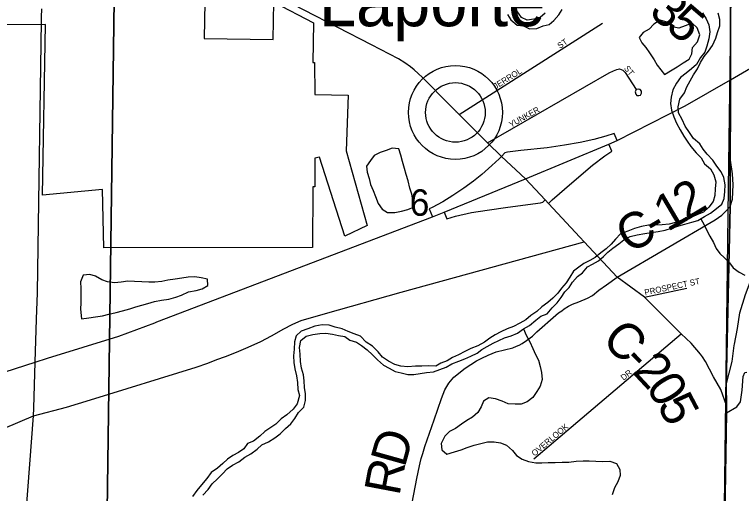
# Model space of a CAD drawing. Extents: x 1857828 to 2277390, y 930619 to 1324581.
# Drawn here: x 2080841 to 2086916, y 1210395 to 1214402 of the extents above; entities that cross this region are included whole.
import ezdxf

# ---------------------------------------------------------------- set-up
doc = ezdxf.new("R2010")
doc.units = 0
for name, color, linetype in [('GM_X_City_Street', 7, 'Continuous'), ('GM_X_Corporation', 7, 'Continuous'), ('GM_X_County_Road', 7, 'Continuous'), ('GM_X_County_Road_Text', 7, 'Continuous'), ('GM_X_Interchange_Ramps', 7, 'Continuous'), ('GM_X_Major_River', 7, 'Continuous'), ('GM_X_Minor_Lake', 7, 'Continuous'), ('GM_X_Minor_River', 7, 'Continuous'), ('GM_X_Section', 7, 'Continuous'), ('GM_X_Section_Text', 7, 'Continuous'), ('GM_X_State_Route', 7, 'Continuous'), ('GM_X_Township', 7, 'Continuous'), ('GM_X_Township_Road', 7, 'Continuous'), ('GM_X_Township_Road_Text', 7, 'Continuous'), ('GM_X_Township_Subdivision', 7, 'Continuous'), ('GM_X_Township_Subdivision_Text', 7, 'Continuous'), ('GM_X_Unincorporated', 7, 'Continuous'), ('GM_X_Unincorporated_Location', 7, 'Continuous'), ('GM_X_Unincorporated_Text', 7, 'Continuous'), ('GM_X_US_Route', 7, 'Continuous')]:
    doc.layers.add(name, color=color, linetype=linetype)

msp = doc.modelspace()

# ---------------------------------------------------------------- linework, layer by layer
at = {"layer": 'GM_X_City_Street'}
msp.add_lwpolyline([(2081066.6, 1214346.6), (2081067.1, 1214378.9), (2081068.2, 1214450.4)], dxfattribs=at)
at = {"layer": 'GM_X_Corporation'}
msp.add_lwpolyline([(2082431.7, 1214504.8), (2082426.4, 1214200.2), (2083003.5, 1214192.8), (2083008.7, 1214504.1), (2083340.5, 1214333.6), (2083332.8, 1214000.9), (2083348.9, 1214000.9), (2083349.6, 1213733.2), (2083627.9, 1213727.4), (2083613.9, 1213261.3), (2083786.8, 1212637.9), (2083600.3, 1212548.9), (2083390.2, 1213209.5), (2083351.1, 1213200.4), (2083351.7, 1212960.8), (2083335.2, 1212960.6), (2083330.6, 1212452.1), (2081588.3, 1212450.2), (2081574.8, 1212939.6), (2081074.2, 1212891.7), (2081100.6, 1214319.6), (2078910.7, 1214305.6)], dxfattribs=at)
at = {"layer": 'GM_X_County_Road'}
for points in [[(2084481.4, 1213642.1), (2084249.4, 1213874.3), (2084213, 1213908.4), (2084181.9, 1213938), (2084150, 1213963.7), (2084103.8, 1213997.9), (2084049, 1214032.5), (2083824.5, 1214148.2), (2082699.2, 1214730.9), (2082586.9, 1214795.9), (2082546.1, 1214823.7), (2082500.7, 1214856.2), (2082438.5, 1214905.4), (2082371.7, 1214977.8), (2082055.3, 1215322), (2081693.4, 1215722.8), (2081081.5, 1216369.5), (2080916.1, 1216542.2), (2080871.6, 1216592.1), (2080789.2, 1216690.2), (2080649.8, 1216892.8), (2080547.6, 1217082.7)], [(2081001.8, 1211108.6), (2081013.7, 1211494.1), (2081024.2, 1211853.7), (2081031.5, 1212075), (2081035.5, 1212267), (2081066.6, 1214346.6)], [(2085565.4, 1212540.5), (2085302.8, 1212822.2), (2085275.7, 1212851.4), (2085111.3, 1213027.7), (2084910, 1213213.6), (2084793.3, 1213328.4), (2084556.9, 1213566.5), (2084481.4, 1213642.1)], [(2085878.9, 1212204), (2086695.4, 1212685.1), (2086753.3, 1212724.5), (2086780, 1212751.2), (2086821.5, 1212795.1), (2086841.4, 1212856.6), (2086847.2, 1212977.1), (2086842.5, 1213068.6), (2086822.7, 1213201.9), (2086823.8, 1213635.3)], [(2086589.8, 1211537.5), (2086575.2, 1211559.4), (2086495.8, 1211654), (2086413.5, 1211730.5), (2086105.7, 1212038.4), (2085878.9, 1212204), (2085602.9, 1212500.2), (2085565.4, 1212540.5)], [(2073594.6, 1207932.1), (2076220, 1209011.3), (2080999.8, 1211044.3), (2081275, 1211117.7), (2081474.9, 1211179.1), (2082358.5, 1211451.5), (2082456.5, 1211486.3), (2082532.4, 1211514.8), (2082604.4, 1211541.4), (2082696.3, 1211576.1), (2082794.2, 1211618.8), (2082898, 1211665.6), (2082987.9, 1211714.3), (2083091.7, 1211771.2), (2083161.6, 1211809.7), (2083191.6, 1211824), (2083235.5, 1211842.3), (2083439.5, 1211899.7), (2084071.3, 1212080.3), (2085602.9, 1212500.2)], [(2086791.5, 1211130), (2086745.3, 1211263.9), (2086684.1, 1211371), (2086649.7, 1211435), (2086616.3, 1211498.2), (2086589.8, 1211537.5)], [(2080937.3, 1210236.7), (2080999.8, 1211044.3), (2081001.8, 1211108.6)]]:
    msp.add_lwpolyline(points, dxfattribs=at)
at = {"layer": 'GM_X_Interchange_Ramps'}
for points in [[(2085877.3, 1213347.3), (2085852.6, 1213406.5), (2085782.4, 1213384.3), (2085683.6, 1213357.4), (2085568.5, 1213331.6), (2085437, 1213309.7), (2085292, 1213287.7), (2085073.7, 1213263.5), (2084961.2, 1213251.3), (2084939.5, 1213245.6), (2084910, 1213213.6)], [(2085302.8, 1212822.2), (2085335, 1212852.2), (2085499, 1212994), (2085671.1, 1213142.6), (2085773.4, 1213221.2), (2085832.5, 1213260), (2085808.1, 1213318.5)], [(2084910, 1213213.6), (2084892.7, 1213194.9), (2084830.8, 1213138.4), (2084747.4, 1213062.8), (2084676.1, 1213007.6), (2084595.3, 1212949.7), (2084505.1, 1212887.5), (2084421.5, 1212834.9), (2084332.4, 1212787.8), (2084306.4, 1212776), (2084333.6, 1212709.4)], [(2084431.2, 1212749.3), (2084454.6, 1212692.1), (2084527.4, 1212713.9), (2084660.1, 1212745.3), (2084790.3, 1212764.5), (2084963.7, 1212789.6), (2085237.6, 1212825.3), (2085255.1, 1212832.3), (2085275.7, 1212851.4)]]:
    msp.add_lwpolyline(points, dxfattribs=at)
at = {"layer": 'GM_X_Major_River'}
for points in [[(2084960, 1214403), (2084988.3, 1214357), (2085042.6, 1214313.1), (2085094.8, 1214307.3), (2085145, 1214283.5), (2085205.1, 1214285.8), (2085259.2, 1214306.1), (2085309.2, 1214318.4), (2085349.2, 1214352.7), (2085389.1, 1214399.1), (2085417, 1214445.4)], [(2085276.8, 1214412.6), (2085234.8, 1214378.3), (2085180.7, 1214361.9), (2085124.6, 1214353.6), (2085078.4, 1214377.5), (2085038.1, 1214433.5)], [(2086591.9, 1214415), (2086620.1, 1214366.9), (2086642.4, 1214316.8), (2086652.7, 1214258.6), (2086644.9, 1214198.4), (2086627.1, 1214136), (2086609.3, 1214087.8), (2086575.3, 1214043.2), (2086539.6, 1213983), (2086497.6, 1213946.6), (2086453.7, 1213910.3), (2086405.7, 1213873.9), (2086373.8, 1213827.6), (2086344, 1213773.2), (2086330.2, 1213710.9), (2086324.4, 1213656.6), (2086332.7, 1213602.5), (2086351, 1213546.3), (2086373.2, 1213492.2), (2086403.6, 1213436.2), (2086433.9, 1213384.1), (2086462.1, 1213342.1), (2086494.4, 1213298.1), (2086536.7, 1213246.1), (2086579, 1213204.1), (2086607.2, 1213152), (2086657.5, 1213112.1), (2086685.8, 1213062), (2086702.1, 1213001.9), (2086696.3, 1212943.6), (2086694.6, 1212887.4), (2086680.7, 1212839.1), (2086642.9, 1212790.8), (2086598.9, 1212748.4), (2086542.9, 1212726), (2086482.9, 1212697.6), (2086418.8, 1212681.2), (2086364.8, 1212662.9), (2086312.7, 1212648.6), (2086252.6, 1212642.3), (2086192.4, 1212640), (2086138.3, 1212639.7), (2086082.2, 1212627.4), (2086022.2, 1212613), (2085966.1, 1212590.7), (2085906.1, 1212568.3), (2085864.2, 1212521.9), (2085826.3, 1212479.6), (2085786.3, 1212443.2), (2085740.4, 1212408.9)], [(2085798.5, 1212415.2), (2085842.4, 1212447.5), (2085890.4, 1212483.9), (2085932.4, 1212516.2), (2085986.4, 1212544.6), (2086044.4, 1212558.9), (2086108.5, 1212569.3), (2086162.6, 1212579.6), (2086220.7, 1212587.9), (2086278.8, 1212598.2), (2086332.9, 1212614.6), (2086392.9, 1212632.9), (2086443, 1212649.2), (2086501.1, 1212665.6), (2086551.1, 1212677.9), (2086607.1, 1212712.3), (2086657.1, 1212740.6), (2086709.1, 1212779), (2086751, 1212815.4), (2086770.9, 1212861.6), (2086778.6, 1212921.9), (2086780.4, 1212978.2), (2086770.1, 1213038.3), (2086745.9, 1213086.4), (2086711.6, 1213134.4), (2086677.3, 1213184.5), (2086628.9, 1213234.4), (2086596.7, 1213274.4), (2086568.4, 1213320.5), (2086516.1, 1213364.4), (2086481.8, 1213414.4), (2086445.5, 1213468.5), (2086421.2, 1213522.6), (2086388.9, 1213578.7), (2086386.7, 1213628.8), (2086402.5, 1213693.2), (2086440.3, 1213745.6), (2086460.2, 1213797.9), (2086488, 1213846.2), (2086515.9, 1213898.6), (2086547.7, 1213948.9), (2086573.6, 1214001.2), (2086605.4, 1214049.6), (2086641.3, 1214095.9), (2086673.2, 1214144.3), (2086701, 1214204.7), (2086716.8, 1214252.9), (2086734.6, 1214307.2), (2086736.4, 1214361.5), (2086722.2, 1214413.6)], [(2085740.4, 1212408.9), (2085694.4, 1212368.5), (2085650.4, 1212344.2), (2085598.4, 1212319.8), (2085556.4, 1212289.5), (2085512.5, 1212255.2), (2085480.6, 1212204.8), (2085450.7, 1212158.5), (2085412.8, 1212112.1), (2085380.9, 1212069.8), (2085341, 1212029.4), (2085297.1, 1211993.1), (2085249.1, 1211956.7), (2085205.2, 1211918.3), (2085157.2, 1211884), (2085115.3, 1211847.6), (2085063.3, 1211819.3), (2085011.3, 1211790.9), (2084959.2, 1211772.6), (2084905.2, 1211748.2), (2084857.2, 1211721.9), (2084813.2, 1211693.6), (2084769.2, 1211661.2), (2084713.2, 1211630.8), (2084653.2, 1211608.4), (2084605.2, 1211582.1), (2084551.2, 1211555.8), (2084501.1, 1211531.4), (2084457.2, 1211505.1), (2084405.1, 1211484.8), (2084361.1, 1211460.5), (2084299, 1211462.2), (2084244.8, 1211459.9), (2084192.7, 1211459.6), (2084128.6, 1211455.3), (2084068.4, 1211459), (2084018.3, 1211472.8), (2083966, 1211500.7), (2083915.8, 1211534.6), (2083879.5, 1211580.6), (2083833.2, 1211626.6), (2083780.9, 1211662.4), (2083732.6, 1211710.4), (2083678.4, 1211730.2), (2083628.2, 1211750.1), (2083577.9, 1211773.9), (2083521.7, 1211787.7), (2083471.6, 1211803.5), (2083411.4, 1211805.2), (2083349.3, 1211794.9), (2083291.3, 1211772.5), (2083237.2, 1211752.2), (2083193.3, 1211713.8), (2083181.5, 1211663.6), (2083177.7, 1211603.3), (2083171.9, 1211547.1), (2083176.2, 1211490.9), (2083184.4, 1211438.7), (2083198.7, 1211380.5), (2083205, 1211322.3), (2083209.2, 1211264.1), (2083221.5, 1211214), (2083203.7, 1211145.6), (2083169.8, 1211099.3), (2083115.9, 1211052.8), (2083069.9, 1211018.5), (2083024, 1210976.1), (2082982, 1210947.8), (2082934.1, 1210913.4), (2082890.1, 1210875), (2082838.2, 1210832.6), (2082788.1, 1210814.3), (2082756.3, 1210768), (2082712.3, 1210737.6), (2082664.3, 1210713.3), (2082620.3, 1210683), (2082580.4, 1210646.6), (2082538.4, 1210606.3), (2082484.4, 1210571.9), (2082446.6, 1210521.5), (2082402.7, 1210467.1), (2082364.8, 1210418.7), (2082328.9, 1210370.3)], [(2082415.1, 1210380.8), (2082459, 1210427.2), (2082492.9, 1210475.6), (2082536.8, 1210517.9), (2082578.7, 1210558.3), (2082618.6, 1210602.7), (2082662.6, 1210633), (2082716.6, 1210659.3), (2082766.6, 1210697.7), (2082814.6, 1210728.1), (2082868.5, 1210766.5), (2082908.5, 1210802.8), (2082962.5, 1210827.2), (2083016.5, 1210859.6), (2083060.4, 1210893.9), (2083106.4, 1210938.3), (2083150.3, 1210976.7), (2083184.2, 1211023.1), (2083214.1, 1211071.4), (2083258, 1211117.8), (2083273.8, 1211174.1), (2083273.5, 1211228.3), (2083265.3, 1211282.5), (2083261, 1211336.6), (2083254.8, 1211388.8), (2083240.5, 1211443), (2083230.3, 1211499.1), (2083228, 1211561.4), (2083223.8, 1211615.6), (2083233.5, 1211673.8), (2083277.5, 1211712.2), (2083333.6, 1211726.5), (2083393.7, 1211734.9), (2083443.8, 1211735.1), (2083497.9, 1211729.3), (2083548.1, 1211717.6), (2083600.3, 1211709.8), (2083644.5, 1211677.9), (2083698.7, 1211660.1), (2083740.9, 1211632.1), (2083789.2, 1211596.2), (2083831.5, 1211554.3), (2083875.7, 1211512.3), (2083924.1, 1211468.4), (2083972.3, 1211442.5), (2084022.5, 1211414.6), (2084072.7, 1211404.8), (2084128.9, 1211391.1), (2084179, 1211391.3), (2084231.1, 1211399.6), (2084283.2, 1211405.9), (2084341.3, 1211414.2), (2084395.3, 1211432.5), (2084447.4, 1211452.8), (2084495.4, 1211479.2), (2084555.4, 1211501.6), (2084605.4, 1211521.9), (2084655.5, 1211544.2), (2084707.5, 1211568.6), (2084747.5, 1211598.9), (2084791.4, 1211625.2), (2084841.4, 1211653.5), (2084887.4, 1211675.9), (2084935.5, 1211698.2), (2084991.5, 1211714.5), (2085043.6, 1211736.8), (2085093.5, 1211771.2), (2085145.5, 1211799.6), (2085197.5, 1211844), (2085239.4, 1211878.3), (2085293.5, 1211896.7), (2085333.3, 1211949.1), (2085377.3, 1211989.5), (2085409.2, 1212035.8), (2085441, 1212082.1), (2085477, 1212118.4), (2085504.8, 1212162.8), (2085544.7, 1212209.1), (2085586.7, 1212241.5), (2085628.6, 1212289.9), (2085672.6, 1212314.2), (2085720.6, 1212342.5), (2085762.5, 1212378.9), (2085798.5, 1212415.2)]]:
    msp.add_lwpolyline(points, dxfattribs=at)
at = {"layer": 'GM_X_Minor_Lake'}
for points in [[(2086272.6, 1213899.9), (2086322.5, 1213932.3), (2086378.5, 1213964.8), (2086430.5, 1213997.3), (2086478.4, 1214027.7), (2086502.2, 1214072.1), (2086508, 1214126.4), (2086547.8, 1214172.8), (2086569.6, 1214231.2), (2086545.2, 1214291.3), (2086504.9, 1214329.3), (2086444.8, 1214306.8), (2086392.8, 1214288.4), (2086338.6, 1214298.1), (2086294.2, 1214338), (2086236, 1214353.7), (2086184, 1214321.3)], [(2086184, 1214321.3), (2086144.1, 1214278.8), (2086094.2, 1214250.4), (2086060.3, 1214210), (2086084.6, 1214166), (2086116.9, 1214126), (2086147.2, 1214081.9), (2086185.6, 1214023.9), (2086212, 1213977.9), (2086272.6, 1213899.9)], [(2084180.8, 1212794.1), (2084168.5, 1212848.3), (2084160.2, 1212900.5), (2084145.9, 1212950.6), (2084131.5, 1213010.8), (2084115.2, 1213064.9), (2084100.9, 1213115.1), (2084082.5, 1213171.2), (2084070.2, 1213225.4), (2084053.8, 1213277.5), (2083997.7, 1213283.2), (2083945.6, 1213264.8), (2083897.6, 1213248.5), (2083845.6, 1213222), (2083815.7, 1213179.6), (2083781.9, 1213133.2), (2083788.2, 1213083)], [(2083788.2, 1213083), (2083804.5, 1213030.9), (2083816.8, 1212980.7), (2083839.1, 1212930.6), (2083857.5, 1212878.5), (2083879.8, 1212822.4), (2083914.2, 1212772.4), (2083958.5, 1212744.5), (2084018.6, 1212746.9), (2084074.7, 1212757.3), (2084126.8, 1212769.7), (2084180.8, 1212794.1)], [(2082401.2, 1212200.6), (2082347, 1212208.3), (2082290.8, 1212203.9), (2082238.7, 1212195.6), (2082184.6, 1212187.2), (2082122.5, 1212178.8), (2082072.4, 1212168.4), (2082012.3, 1212162), (2081962.2, 1212161.7), (2081904, 1212165.4), (2081843.8, 1212169), (2081787.6, 1212170.7), (2081731.5, 1212164.3), (2081677.4, 1212158), (2081617.2, 1212165.6), (2081569, 1212183.4), (2081518.7, 1212213.2), (2081470.4, 1212227), (2081414.3, 1212222.7), (2081392.6, 1212166.3), (2081394.9, 1212110), (2081395.2, 1212059.8), (2081393.5, 1211989.5), (2081391.8, 1211937.2), (2081400.3, 1211856.9)], [(2081400.3, 1211856.9), (2081460.4, 1211863.3), (2081518.5, 1211871.7), (2081574.6, 1211882.1), (2081628.7, 1211896.5), (2081688.8, 1211908.9), (2081742.9, 1211923.3), (2081804.9, 1211939.8), (2081855, 1211956.1), (2081905, 1211970.5), (2081955.1, 1211984.9), (2082009.2, 1212001.3), (2082069.3, 1212011.7), (2082129.4, 1212022.1), (2082187.5, 1212036.5), (2082235.5, 1212054.9), (2082293.5, 1212083.4), (2082357.6, 1212093.8), (2082407.7, 1212108.2), (2082455.7, 1212134.6), (2082453.4, 1212186.8), (2082401.2, 1212200.6)]]:
    msp.add_lwpolyline(points, dxfattribs=at)
at = {"layer": 'GM_X_Minor_River'}
for points in [[(2086577.6, 1212694.2), (2086604.3, 1212642.1), (2086626.6, 1212594.1), (2086653, 1212548), (2086683.3, 1212495.9), (2086703.7, 1212445.8), (2086736, 1212401.8), (2086774.3, 1212365.9), (2086816.6, 1212324), (2086846.9, 1212284), (2086897.3, 1212246.1), (2086945.6, 1212220.3)], [(2085095.8, 1211772.5), (2085117.3, 1211720.9), (2085147.6, 1211664.8), (2085172, 1211608.7), (2085194.3, 1211558.6), (2085218.7, 1211510.6), (2085235, 1211456.4), (2085245.3, 1211406.2), (2085251.6, 1211350), (2085233.9, 1211293.7), (2085206.1, 1211247.3), (2085172.3, 1211196.8), (2085124.3, 1211162.4), (2085076.3, 1211142), (2085024.2, 1211141.7), (2084966, 1211145.4), (2084915.7, 1211167.2), (2084861.5, 1211186.9), (2084805.3, 1211196.6), (2084761.3, 1211168.2), (2084741.5, 1211119.9), (2084713.7, 1211071.5), (2084667.8, 1211033), (2084619.8, 1211004.6), (2084575.8, 1210974.2), (2084525.9, 1210939.8), (2084475.9, 1210913.3), (2084436, 1210874.9), (2084406.2, 1210814.4), (2084412.6, 1210760.2), (2084452.9, 1210724.3), (2084516.9, 1210742.8), (2084573, 1210759.2), (2084625, 1210779.6), (2084681.1, 1210800.1), (2084739.2, 1210814.5), (2084793.2, 1210826.9), (2084849.4, 1210827.2), (2084903.6, 1210817.5), (2084953.8, 1210799.7), (2085002.2, 1210755.8), (2085036.5, 1210713.8), (2085082.8, 1210682), (2085137.1, 1210662.2), (2085197.3, 1210650.5), (2085247.4, 1210652.8), (2085301.6, 1210653.2), (2085359.7, 1210655.5), (2085417.9, 1210657.9), (2085474, 1210656.2), (2085536.2, 1210664.6), (2085592.3, 1210667), (2085642.4, 1210667.3), (2085700.6, 1210665.6), (2085756.8, 1210664), (2085814.9, 1210664.3), (2085871.2, 1210644.6), (2085899.5, 1210596.5), (2085901.8, 1210546.3), (2085882.1, 1210492), (2085854.2, 1210443.6), (2085834.5, 1210385.2)]]:
    msp.add_lwpolyline(points, dxfattribs=at)
at = {"layer": 'GM_X_Section'}
for points in [[(2076344.3, 1215732.7), (2081688.8, 1215745.2), (2081611.5, 1210047.1), (2076246.6, 1210012.2)], [(2086844.8, 1215767), (2086806.5, 1212949.4), (2086771.6, 1210288), (2086769.4, 1210081), (2081611.5, 1210047.1), (2081688.8, 1215745.2)]]:
    msp.add_lwpolyline(points, close=True, dxfattribs=at)
at = {"layer": 'GM_X_State_Route'}
for points in [[(2086857.4, 1211643.8), (2086882.1, 1211774.5), (2086903.1, 1211906.4), (2086950.9, 1212059.5), (2087023.6, 1212253.5), (2087393.1, 1212824.7), (2087525.4, 1213089.5), (2087611.3, 1213406.7), (2087640.8, 1213663.6), (2087647.8, 1213865.6), (2087640.7, 1213980.6), (2087639.6, 1213999), (2087621.7, 1214291.1)], [(2086788.6, 1211286.5), (2086788.2, 1211303.5), (2086840, 1211499.1), (2086855.3, 1211633), (2086857.4, 1211643.8)], [(2086784.2, 1210601.2), (2086792.2, 1211070.7), (2086791.5, 1211130), (2086788.6, 1211286.5)], [(2086747.3, 1208327.6), (2086747.3, 1208327.6), (2086750.2, 1208539), (2086754.4, 1208841.7), (2086784.2, 1210601.2)]]:
    msp.add_lwpolyline(points, dxfattribs=at)
at = {"layer": 'GM_X_Township'}
for points in [[(2067771.4, 1221365.5), (2071559.9, 1221318), (2072926.4, 1221321.4), (2074729.4, 1221325.9), (2074869.3, 1221327.3), (2075410.3, 1221332.8), (2076347.8, 1221341.6), (2076980.3, 1221347.6), (2077896.6, 1221356.3), (2078876.9, 1221357.6), (2084360.8, 1221334.4), (2086459.3, 1221290.7), (2086885, 1221290.7), (2086885.2, 1220532.6), (2086868.6, 1218191.5), (2086826, 1214466.2), (2086824.4, 1213856.5), (2086823.8, 1213635.3), (2086822.7, 1213201.9), (2086821.5, 1212795.1), (2086788.3, 1211303.5), (2086791.5, 1211130), (2086792.2, 1211070.7), (2086754.4, 1208841.7)], [(2086754.4, 1208841.7), (2086792.2, 1211070.7), (2086791.5, 1211130), (2086788.3, 1211303.5), (2086821.5, 1212795.1), (2086822.7, 1213201.9), (2086823.8, 1213635.3), (2086824.4, 1213856.5), (2086826, 1214466.2), (2086868.6, 1218191.5), (2086885.2, 1220532.6), (2086885, 1221290.7), (2090249.5, 1221329.8)]]:
    msp.add_lwpolyline(points, dxfattribs=at)
at = {"layer": 'GM_X_Township_Road'}
msp.add_lwpolyline([(2084112.4, 1210040), (2084203.9, 1210520.1), (2084225.4, 1210626.6), (2084231.3, 1210650.7), (2084239.1, 1210686.9), (2084252.9, 1210729.1), (2084270.6, 1210787.4), (2084347.4, 1211010.6), (2084408.6, 1211189.5), (2084436.2, 1211261.9), (2084469.9, 1211318.3), (2084511.7, 1211368.8), (2084607.4, 1211443.6), (2084703.2, 1211504.4), (2084747.1, 1211526.7), (2084799.1, 1211551.2), (2084865, 1211579.6), (2085005, 1211614.6), (2085034.9, 1211628.9), (2085059, 1211637), (2085082.9, 1211649.2), (2085120.8, 1211673.6), (2085168.7, 1211710), (2085206.5, 1211746.3), (2085366, 1211887.8), (2085387.9, 1211906), (2085413.8, 1211924.2), (2085435.8, 1211940.4), (2085471.7, 1211962.7), (2085505.6, 1211978.9), (2085557.6, 1211997.3), (2085629.5, 1212027.9), (2085671.5, 1212052.2), (2085723.3, 1212094.7), (2085789.1, 1212141.2), (2085878.9, 1212204)], dxfattribs=at)
at = {"layer": 'GM_X_Township_Subdivision'}
for points in [[(2084556.9, 1213566.5), (2085756.1, 1214330.2)], [(2084793.3, 1213328.4), (2085812, 1213913.2), (2085846, 1213931.5), (2085873.9, 1213941.6), (2085898, 1213947.8), (2085926, 1213937.9), (2085944.1, 1213917.9), (2085976.4, 1213870), (2086036.9, 1213776), (2086028.9, 1213755.6), (2086033.1, 1213735.9), (2086043.2, 1213725.6), (2086059, 1213723.6), (2086073.1, 1213728.1), (2086080.7, 1213744.3), (2086081, 1213760.2), (2086068.9, 1213774.2), (2086053.1, 1213776.4), (2086038.9, 1213774)], [(2086105.7, 1212038.4), (2086459, 1212112.9)], [(2085180.8, 1210685.4), (2086413.5, 1211730.5)], [(2086792.2, 1211070.7), (2086878.3, 1211120.4), (2086908.9, 1211162.5), (2086922.2, 1211260.1), (2086929.9, 1211372.9), (2086945.2, 1211407.3), (2086960.8, 1211411.1)]]:
    msp.add_lwpolyline(points, dxfattribs=at)
at = {"layer": 'GM_X_Unincorporated'}
for radius in [392.8, 249]:
    msp.add_circle((2084525.8, 1213583), radius, dxfattribs=at)
at = {"layer": 'GM_X_Unincorporated_Location'}
msp.add_line((2084525.8, 1213583), (2084525.8, 1213583), dxfattribs=at)
at = {"layer": 'GM_X_US_Route'}
for points in [[(2082030.8, 1211830.4), (2084333.6, 1212709.4), (2084431.2, 1212749.3), (2085111.3, 1213027.7), (2085808.1, 1213318.5), (2085877.3, 1213347.3), (2086445.1, 1213639.1), (2086824.4, 1213856.5), (2086991, 1213951.9), (2087178.8, 1214075.9), (2087496.5, 1214310)], [(2081116, 1211525.8), (2081712.6, 1211710.2), (2082013.4, 1211823.7), (2082030.8, 1211830.4)], [(2073483.9, 1208952.2), (2073498.1, 1208959.3), (2073590.4, 1208999.9), (2074374.8, 1209322.4), (2074479.3, 1209360.1), (2075170.3, 1209609.3), (2076226, 1209942.8), (2077455.5, 1210333.7), (2079722.9, 1211077.9), (2081013.7, 1211494.1), (2081116, 1211525.8)]]:
    msp.add_lwpolyline(points, dxfattribs=at)

# ---------------------------------------------------------------- texts
at = {"layer": 'GM_X_County_Road_Text'}
for s, rotation, p in [('2', 30.75611, (2086457.4, 1212674.4)), ('1', 30.51113, (2086298.2, 1212580.7)), ('C', 30.50517, (2085982.3, 1212394.5)), ('-', 30.50518, (2086193, 1212518.7)), ('C', 314.56669, (2085737.4, 1211672.4)), ('-', 314.33207, (2085910.1, 1211497.1)), ('2', 313.04562, (2085995, 1211410.3)), ('0', 302.28121, (2086112, 1211287)), ('5', 297.70547, (2086207.5, 1211136.3))]:
    msp.add_text(s, height=300, rotation=rotation, dxfattribs=at).set_placement(p)
at = {"layer": 'GM_X_Section_Text'}
msp.add_text('6', height=221, rotation=0.00001, dxfattribs=at).set_placement((2084144.1, 1212718.5))
at = {"layer": 'GM_X_Township_Road_Text'}
for s, rotation, p in [('3', 319.22485, (2086133, 1214409)), ('5', 319.29876, (2086273.3, 1214288.1)), ('D', 74.35031, (2084101, 1210604.2)), ('R', 79.21058, (2084056.4, 1210368.7))]:
    msp.add_text(s, height=300, rotation=rotation, dxfattribs=at).set_placement(p)
at = {"layer": 'GM_X_Township_Subdivision_Text'}
for s, rotation, p in [('ST', 34.70215, (2085399.3, 1214114.1)), ('JERROL', 32.12355, (2084862.9, 1213775.5)), ('ST', 309.80916, (2085931.1, 1213949.6)), ('YUNKER', 29.24909, (2084990.9, 1213454.6)), ('PROSPECT ST', 11.81973, (2086111.1, 1212052)), ('DR', 38.65625, (2085931.2, 1211337.3)), ('OVERLOOK', 40.19477, (2085187.4, 1210703.5))]:
    msp.add_text(s, height=50, rotation=rotation, dxfattribs=at).set_placement(p)
at = {"layer": 'GM_X_Unincorporated_Text'}
msp.add_text('Laporte', height=417, rotation=0.00001, dxfattribs=at).set_placement((2083385.1, 1214304.1))

doc.saveas('drawing.dxf')
